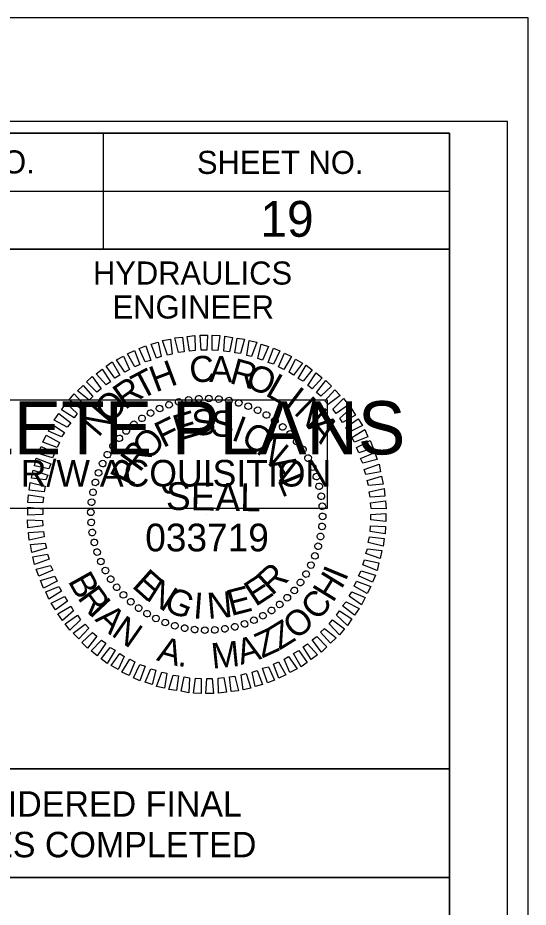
# Model space of a CAD drawing. Extents: x 1779926 to 1781610, y 602514 to 621564.
# Drawn here: x 1781499.5 to 1781610, y 603422 to 603614.5 of the extents above; entities that cross this region are included whole.
import ezdxf

# ---------------------------------------------------------------- set-up
doc = ezdxf.new("R2010")
doc.units = 0
for name, color, linetype in [('Old_Level_58', 7, 'Continuous'), ('Sheet Data Field CELL', 7, 'Continuous'), ('Sheet Plot Border Inside CELL', 7, 'Continuous'), ('Sheet Plot Border Outside CELL', 7, 'Continuous'), ('Sheet Professional Seal CELL', 7, 'Continuous'), ('Sheet Profile CELL', 7, 'Continuous'), ('Sheet Profile Grid Major CELL', 7, 'Continuous'), ('Sheet Profile Grid Minor CELL', 7, 'Continuous'), ('Sheet Sticker Exception Certification CELL', 7, 'Continuous'), ('Sheet Sticker Incomplete CELL', 7, 'Continuous')]:
    doc.layers.add(name, color=color, linetype=linetype)

msp = doc.modelspace()

# ---------------------------------------------------------------- linework, layer by layer
at = {"layer": 'Old_Level_58'}
msp.add_lwpolyline([(1781392.96, 603428.4), (1781592.95, 603428.4), (1781592.95, 603364.45), (1781392.96, 603364.45)], close=True, dxfattribs=at)
at = {"layer": 'Sheet Plot Border Inside CELL'}
msp.add_lwpolyline([(1779938.96, 602536.9), (1781605.46, 602536.9), (1781605.46, 603592), (1779938.96, 603592)], close=True, dxfattribs=at)
at = {"layer": 'Sheet Plot Border Outside CELL'}
msp.add_lwpolyline([(1779925.96, 602514.45), (1781609.96, 602514.45), (1781609.96, 603614.45), (1779925.96, 603614.45)], close=True, dxfattribs=at)
at = {"layer": 'Sheet Professional Seal CELL'}
for p, q in [((1781538.64, 603532.03), (1781538.64, 603532.03)), ((1781540.84, 603532.08), (1781540.84, 603532.08)), ((1781543.04, 603531.93), (1781543.04, 603531.93)), ((1781530.19, 603529.93), (1781530.19, 603529.93)), ((1781532.19, 603530.73), (1781532.19, 603530.73)), ((1781534.29, 603531.33), (1781534.29, 603531.33)), ((1781536.49, 603531.73), (1781536.49, 603531.73)), ((1781545.19, 603531.58), (1781545.19, 603531.58)), ((1781547.29, 603531.13), (1781547.29, 603531.13)), ((1781549.39, 603530.43), (1781549.39, 603530.43)), ((1781528.24, 603528.93), (1781528.24, 603528.93)), ((1781551.39, 603529.53), (1781551.39, 603529.53)), ((1781553.34, 603528.53), (1781553.34, 603528.53)), ((1781524.59, 603526.53), (1781524.59, 603526.53)), ((1781526.34, 603527.78), (1781526.34, 603527.78)), ((1781555.14, 603527.28), (1781555.14, 603527.28)), ((1781522.94, 603525.03), (1781522.94, 603525.03)), ((1781556.89, 603525.93), (1781556.89, 603525.93)), ((1781558.44, 603524.43), (1781558.44, 603524.43)), ((1781521.44, 603523.48), (1781521.44, 603523.48)), ((1781559.94, 603522.78), (1781559.94, 603522.78)), ((1781520.09, 603521.73), (1781520.09, 603521.73)), ((1781561.19, 603521.03), (1781561.19, 603521.03)), ((1781518.84, 603519.93), (1781518.84, 603519.93)), ((1781562.34, 603519.13), (1781562.34, 603519.13)), ((1781517.84, 603517.98), (1781517.84, 603517.98)), ((1781563.34, 603517.18), (1781563.34, 603517.18)), ((1781516.94, 603515.98), (1781516.94, 603515.98)), ((1781564.14, 603515.18), (1781564.14, 603515.18)), ((1781516.24, 603513.88), (1781516.24, 603513.88)), ((1781564.74, 603513.08), (1781564.74, 603513.08)), ((1781515.79, 603511.78), (1781515.79, 603511.78)), ((1781565.14, 603510.88), (1781565.14, 603510.88)), ((1781515.44, 603509.63), (1781515.44, 603509.63)), ((1781565.44, 603508.73), (1781565.44, 603508.73)), ((1781515.29, 603507.43), (1781515.29, 603507.43)), ((1781540.39, 603506.98), (1781540.39, 603506.98)), ((1781515.34, 603505.23), (1781515.34, 603505.23)), ((1781565.49, 603506.53), (1781565.49, 603506.53)), ((1781515.64, 603503.08), (1781515.64, 603503.08)), ((1781565.34, 603504.33), (1781565.34, 603504.33)), ((1781564.99, 603502.18), (1781564.99, 603502.18)), ((1781516.04, 603500.88), (1781516.04, 603500.88)), ((1781564.54, 603500.08), (1781564.54, 603500.08)), ((1781516.64, 603498.78), (1781516.64, 603498.78)), ((1781563.84, 603497.98), (1781563.84, 603497.98)), ((1781517.44, 603496.78), (1781517.44, 603496.78)), ((1781562.94, 603495.98), (1781562.94, 603495.98)), ((1781518.44, 603494.83), (1781518.44, 603494.83)), ((1781561.94, 603494.03), (1781561.94, 603494.03)), ((1781519.59, 603492.93), (1781519.59, 603492.93)), ((1781560.69, 603492.23), (1781560.69, 603492.23)), ((1781520.84, 603491.18), (1781520.84, 603491.18)), ((1781522.34, 603489.53), (1781522.34, 603489.53)), ((1781559.34, 603490.48), (1781559.34, 603490.48)), ((1781523.89, 603488.03), (1781523.89, 603488.03)), ((1781557.84, 603488.93), (1781557.84, 603488.93)), ((1781525.64, 603486.68), (1781525.64, 603486.68)), ((1781554.44, 603486.18), (1781554.44, 603486.18)), ((1781556.19, 603487.43), (1781556.19, 603487.43)), ((1781527.44, 603485.43), (1781527.44, 603485.43)), ((1781529.39, 603484.43), (1781529.39, 603484.43)), ((1781550.59, 603484.03), (1781550.59, 603484.03)), ((1781552.54, 603485.03), (1781552.54, 603485.03)), ((1781531.39, 603483.53), (1781531.39, 603483.53)), ((1781533.49, 603482.83), (1781533.49, 603482.83)), ((1781535.59, 603482.38), (1781535.59, 603482.38)), ((1781537.74, 603482.03), (1781537.74, 603482.03)), ((1781539.94, 603481.88), (1781539.94, 603481.88)), ((1781542.14, 603481.93), (1781542.14, 603481.93)), ((1781544.29, 603482.23), (1781544.29, 603482.23)), ((1781546.49, 603482.63), (1781546.49, 603482.63)), ((1781548.59, 603483.23), (1781548.59, 603483.23))]:
    msp.add_line(p, q, dxfattribs=at)
for points in [[(1781534.29, 603541.98), (1781533.49, 603545.18), (1781535.14, 603545.33), (1781535.49, 603542.13)], [(1781536.69, 603542.28), (1781536.14, 603545.48), (1781537.84, 603545.68), (1781537.89, 603542.43)], [(1781539.19, 603542.53), (1781538.94, 603545.78), (1781540.59, 603545.73), (1781540.39, 603542.48)], [(1781541.59, 603542.48), (1781541.59, 603545.73), (1781543.24, 603545.68), (1781542.79, 603542.43)], [(1781544.09, 603542.33), (1781544.29, 603545.58), (1781545.94, 603545.28), (1781545.29, 603542.13)], [(1781527.04, 603539.98), (1781525.74, 603542.88), (1781527.24, 603543.48), (1781528.29, 603540.28)], [(1781529.49, 603540.78), (1781528.34, 603543.78), (1781529.89, 603544.23), (1781530.54, 603541.13)], [(1781531.89, 603541.43), (1781530.84, 603544.58), (1781532.54, 603544.93), (1781532.94, 603541.68)], [(1781546.49, 603541.93), (1781546.94, 603545.13), (1781548.59, 603544.88), (1781547.69, 603541.78)], [(1781549.04, 603541.38), (1781549.54, 603544.63), (1781551.24, 603544.23), (1781550.09, 603541.13)], [(1781551.44, 603540.73), (1781552.19, 603543.83), (1781553.74, 603543.33), (1781552.49, 603540.38)], [(1781524.84, 603538.93), (1781523.24, 603541.73), (1781524.79, 603542.43), (1781525.94, 603539.38)], [(1781553.69, 603539.83), (1781554.84, 603542.98), (1781556.24, 603542.38), (1781554.84, 603539.48)], [(1781555.94, 603538.88), (1781557.19, 603541.83), (1781558.74, 603541.13), (1781557.04, 603538.33)], [(1781520.49, 603536.48), (1781518.64, 603539.03), (1781519.94, 603539.98), (1781521.59, 603537.08)], [(1781522.69, 603537.73), (1781520.84, 603540.43), (1781522.39, 603541.23), (1781523.64, 603538.33)], [(1781558.24, 603537.73), (1781559.59, 603540.58), (1781561.09, 603539.73), (1781559.19, 603537.13)], [(1781518.59, 603534.98), (1781516.44, 603537.38), (1781517.79, 603538.43), (1781519.54, 603535.63)], [(1781560.19, 603536.38), (1781561.94, 603539.28), (1781563.24, 603538.23), (1781561.29, 603535.78)], [(1781562.24, 603534.88), (1781564.09, 603537.63), (1781565.39, 603536.53), (1781563.19, 603534.18)], [(1781516.59, 603533.43), (1781514.39, 603535.63), (1781515.59, 603536.83), (1781517.54, 603534.13)], [(1781564.14, 603533.33), (1781566.19, 603535.93), (1781567.39, 603534.73), (1781565.09, 603532.58)], [(1781514.94, 603531.68), (1781512.39, 603533.73), (1781513.64, 603534.88), (1781515.74, 603532.48)], [(1781565.94, 603531.58), (1781568.09, 603533.93), (1781569.29, 603532.73), (1781566.69, 603530.78)], [(1781513.19, 603529.78), (1781510.59, 603531.73), (1781511.69, 603533.03), (1781513.89, 603530.68)], [(1781567.69, 603529.78), (1781569.99, 603532.03), (1781571.04, 603530.68), (1781568.39, 603528.78)], [(1781511.69, 603527.88), (1781508.99, 603529.58), (1781509.94, 603531.03), (1781512.34, 603528.83)], [(1781569.19, 603527.83), (1781571.64, 603529.93), (1781572.59, 603528.48), (1781569.79, 603526.88)], [(1781510.19, 603525.88), (1781507.39, 603527.38), (1781508.39, 603528.78), (1781510.99, 603526.78)], [(1781508.99, 603523.73), (1781506.14, 603524.98), (1781506.89, 603526.53), (1781509.59, 603524.68)], [(1781570.49, 603525.78), (1781573.14, 603527.68), (1781574.09, 603526.18), (1781571.19, 603524.78)], [(1781507.99, 603521.43), (1781504.89, 603522.58), (1781505.64, 603524.13), (1781508.49, 603522.53)], [(1781571.79, 603523.58), (1781574.59, 603525.33), (1781575.24, 603523.78), (1781572.39, 603522.63)], [(1781572.79, 603521.43), (1781575.74, 603522.93), (1781576.39, 603521.33), (1781573.29, 603520.33)], [(1781506.99, 603519.23), (1781503.89, 603520.13), (1781504.54, 603521.68), (1781507.54, 603520.28)], [(1781573.69, 603519.08), (1781576.74, 603520.38), (1781577.29, 603518.83), (1781574.19, 603518.03)], [(1781506.24, 603516.83), (1781503.14, 603517.48), (1781503.49, 603519.13), (1781506.64, 603517.88)], [(1781505.59, 603514.43), (1781502.49, 603514.83), (1781502.84, 603516.53), (1781505.99, 603515.48)], [(1781574.49, 603516.68), (1781577.69, 603517.83), (1781577.99, 603516.18), (1781574.84, 603515.63)], [(1781575.09, 603514.28), (1781578.24, 603515.23), (1781578.54, 603513.53), (1781575.39, 603513.23)], [(1781505.19, 603511.88), (1781501.99, 603512.18), (1781502.19, 603513.88), (1781505.44, 603513.08)], [(1781575.54, 603511.88), (1781578.79, 603512.58), (1781578.94, 603510.88), (1781575.74, 603510.68)], [(1781504.94, 603509.48), (1781501.69, 603509.58), (1781501.79, 603511.23), (1781505.04, 603510.68)], [(1781575.84, 603509.48), (1781579.09, 603509.88), (1781579.19, 603508.18), (1781575.94, 603508.28)], [(1781504.89, 603506.98), (1781501.64, 603506.83), (1781501.64, 603508.53), (1781504.89, 603508.18)], [(1781575.89, 603506.98), (1781579.14, 603507.13), (1781579.14, 603505.43), (1781575.89, 603505.78)], [(1781504.94, 603504.48), (1781501.69, 603504.08), (1781501.59, 603505.78), (1781504.84, 603505.68)], [(1781505.24, 603502.08), (1781501.99, 603501.38), (1781501.84, 603503.08), (1781505.04, 603503.28)], [(1781575.84, 603504.48), (1781579.09, 603504.38), (1781578.99, 603502.73), (1781575.74, 603503.28)], [(1781575.59, 603502.08), (1781578.79, 603501.78), (1781578.59, 603500.08), (1781575.34, 603500.88)], [(1781505.69, 603499.68), (1781502.54, 603498.73), (1781502.24, 603500.43), (1781505.39, 603500.73)], [(1781575.19, 603499.53), (1781578.29, 603499.13), (1781577.94, 603497.43), (1781574.79, 603498.48)], [(1781506.29, 603497.28), (1781503.09, 603496.13), (1781502.79, 603497.78), (1781505.94, 603498.33)], [(1781574.54, 603497.13), (1781577.64, 603496.48), (1781577.29, 603494.83), (1781574.14, 603496.08)], [(1781507.09, 603494.88), (1781504.04, 603493.58), (1781503.49, 603495.13), (1781506.59, 603495.93)], [(1781507.99, 603492.53), (1781505.04, 603491.03), (1781504.39, 603492.63), (1781507.49, 603493.63)], [(1781573.79, 603494.73), (1781576.89, 603493.83), (1781576.24, 603492.28), (1781573.24, 603493.68)], [(1781572.79, 603492.53), (1781575.89, 603491.38), (1781575.14, 603489.83), (1781572.29, 603491.43)], [(1781508.99, 603490.38), (1781506.19, 603488.63), (1781505.54, 603490.18), (1781508.39, 603491.33)], [(1781571.79, 603490.23), (1781574.64, 603488.98), (1781573.89, 603487.43), (1781571.19, 603489.28)], [(1781510.29, 603488.18), (1781507.64, 603486.28), (1781506.69, 603487.78), (1781509.59, 603489.18)], [(1781570.59, 603488.08), (1781573.39, 603486.58), (1781572.39, 603485.18), (1781569.79, 603487.18)], [(1781511.59, 603486.13), (1781509.14, 603484.03), (1781508.19, 603485.48), (1781510.99, 603487.08)], [(1781569.09, 603486.08), (1781571.79, 603484.38), (1781570.84, 603482.93), (1781568.44, 603485.13)], [(1781513.09, 603484.18), (1781510.79, 603481.93), (1781509.74, 603483.28), (1781512.39, 603485.18)], [(1781567.59, 603484.18), (1781570.19, 603482.23), (1781569.09, 603480.93), (1781566.89, 603483.28)], [(1781514.84, 603482.38), (1781512.69, 603480.03), (1781511.49, 603481.23), (1781514.09, 603483.18)], [(1781565.84, 603482.28), (1781568.39, 603480.23), (1781567.14, 603479.08), (1781565.04, 603481.48)], [(1781516.64, 603480.63), (1781514.59, 603478.03), (1781513.39, 603479.23), (1781515.69, 603481.38)], [(1781564.19, 603480.53), (1781566.39, 603478.33), (1781565.19, 603477.13), (1781563.24, 603479.83)], [(1781518.54, 603479.08), (1781516.69, 603476.33), (1781515.39, 603477.43), (1781517.59, 603479.78)], [(1781520.59, 603477.58), (1781518.84, 603474.68), (1781517.54, 603475.73), (1781519.49, 603478.18)], [(1781562.19, 603478.98), (1781564.34, 603476.58), (1781562.99, 603475.53), (1781561.24, 603478.33)], [(1781522.54, 603476.23), (1781521.19, 603473.38), (1781519.69, 603474.23), (1781521.59, 603476.83)], [(1781558.09, 603476.23), (1781559.94, 603473.53), (1781558.39, 603472.73), (1781557.14, 603475.63)], [(1781560.29, 603477.48), (1781562.14, 603474.93), (1781560.84, 603473.98), (1781559.19, 603476.88)], [(1781524.84, 603475.08), (1781523.59, 603472.13), (1781522.04, 603472.83), (1781523.74, 603475.63)], [(1781527.09, 603474.13), (1781525.94, 603470.98), (1781524.54, 603471.58), (1781525.94, 603474.48)], [(1781555.94, 603475.03), (1781557.54, 603472.23), (1781555.99, 603471.53), (1781554.84, 603474.58)], [(1781529.34, 603473.23), (1781528.59, 603470.13), (1781527.04, 603470.63), (1781528.29, 603473.58)], [(1781531.74, 603472.58), (1781531.24, 603469.33), (1781529.54, 603469.73), (1781530.69, 603472.83)], [(1781534.29, 603472.03), (1781533.84, 603468.83), (1781532.19, 603469.08), (1781533.09, 603472.18)], [(1781548.89, 603472.53), (1781549.94, 603469.38), (1781548.24, 603469.03), (1781547.84, 603472.28)], [(1781551.29, 603473.18), (1781552.44, 603470.18), (1781550.89, 603469.73), (1781550.24, 603472.83)], [(1781553.74, 603473.98), (1781555.04, 603471.08), (1781553.54, 603470.48), (1781552.49, 603473.68)], [(1781536.69, 603471.63), (1781536.49, 603468.38), (1781534.84, 603468.68), (1781535.49, 603471.83)], [(1781539.19, 603471.48), (1781539.19, 603468.23), (1781537.54, 603468.28), (1781537.99, 603471.53)], [(1781541.59, 603471.43), (1781541.84, 603468.18), (1781540.19, 603468.23), (1781540.39, 603471.48)], [(1781544.09, 603471.68), (1781544.64, 603468.48), (1781542.94, 603468.28), (1781542.89, 603471.53)], [(1781546.49, 603471.98), (1781547.29, 603468.78), (1781545.64, 603468.63), (1781545.29, 603471.83)]]:
    msp.add_lwpolyline(points, close=True, dxfattribs=at)
for centre, major_axis in [((1781534.33, 603531.31), (-0.174, 0.699)), ((1781536.47, 603531.75), (-0.113, 0.711)), ((1781538.65, 603532), (-0.05, 0.718)), ((1781540.83, 603532.05), (0.013, 0.72)), ((1781543.02, 603531.92), (0.075, 0.716)), ((1781545.18, 603531.6), (0.137, 0.707)), ((1781547.31, 603531.09), (0.198, 0.692)), ((1781530.19, 603529.89), (-0.293, 0.658)), ((1781532.23, 603530.69), (-0.234, 0.681)), ((1781549.38, 603530.39), (0.258, 0.672)), ((1781551.39, 603529.52), (0.316, 0.647)), ((1781526.37, 603527.77), (-0.403, 0.597)), ((1781528.24, 603528.91), (-0.349, 0.63)), ((1781553.31, 603528.48), (0.371, 0.617)), ((1781555.14, 603527.27), (0.423, 0.582)), ((1781524.61, 603526.47), (-0.453, 0.56)), ((1781556.85, 603525.91), (0.472, 0.543)), ((1781521.47, 603523.43), (-0.543, 0.472)), ((1781522.97, 603525.02), (-0.5, 0.518)), ((1781558.44, 603524.4), (0.518, 0.5)), ((1781520.1, 603521.72), (-0.582, 0.423)), ((1781559.89, 603522.76), (0.56, 0.453)), ((1781518.9, 603519.9), (-0.617, 0.371)), ((1781561.19, 603521), (0.597, 0.403)), ((1781517.85, 603517.97), (-0.647, 0.316)), ((1781562.33, 603519.14), (0.63, 0.349)), ((1781516.98, 603515.97), (-0.672, 0.258)), ((1781563.31, 603517.18), (0.658, 0.293)), ((1781516.29, 603513.89), (-0.692, 0.198)), ((1781564.11, 603515.14), (0.681, 0.234)), ((1781515.78, 603511.76), (-0.707, 0.137)), ((1781564.73, 603513.05), (0.699, 0.174)), ((1781565.17, 603510.9), (0.711, 0.113)), ((1781515.45, 603509.6), (-0.716, 0.075)), ((1781565.41, 603508.73), (0.718, 0.05)), ((1781515.32, 603507.42), (-0.72, 0.013)), ((1781565.47, 603506.54), (0.72, -0.013)), ((1781515.38, 603505.23), (-0.718, -0.05)), ((1781565.34, 603504.36), (0.716, -0.075)), ((1781515.62, 603503.06), (-0.711, -0.113)), ((1781565.01, 603502.19), (0.707, -0.137)), ((1781516.06, 603500.91), (-0.699, -0.174)), ((1781516.68, 603498.81), (-0.681, -0.234)), ((1781564.5, 603500.07), (0.692, -0.198)), ((1781517.48, 603496.78), (-0.658, -0.293)), ((1781563.81, 603497.99), (0.672, -0.258)), ((1781518.46, 603494.82), (-0.63, -0.349)), ((1781562.94, 603495.98), (0.647, -0.316)), ((1781519.6, 603492.95), (-0.597, -0.403)), ((1781561.89, 603494.06), (0.617, -0.371)), ((1781520.9, 603491.2), (-0.56, -0.453)), ((1781560.68, 603492.24), (0.582, -0.423)), ((1781522.35, 603489.56), (-0.518, -0.5)), ((1781557.82, 603488.94), (0.5, -0.518)), ((1781559.32, 603490.52), (0.543, -0.472)), ((1781523.94, 603488.05), (-0.472, -0.543)), ((1781525.65, 603486.69), (-0.423, -0.582)), ((1781556.18, 603487.49), (0.453, -0.56)), ((1781527.48, 603485.48), (-0.371, -0.617)), ((1781552.55, 603485.04), (0.349, -0.63)), ((1781554.42, 603486.19), (0.403, -0.597)), ((1781529.4, 603484.44), (-0.316, -0.647)), ((1781531.41, 603483.56), (-0.258, -0.672)), ((1781533.48, 603482.87), (-0.198, -0.692)), ((1781548.56, 603483.27), (0.234, -0.681)), ((1781550.6, 603484.07), (0.293, -0.658)), ((1781535.61, 603482.36), (-0.137, -0.707)), ((1781537.77, 603482.04), (-0.075, -0.716)), ((1781539.96, 603481.9), (-0.013, -0.72)), ((1781542.14, 603481.96), (0.05, -0.718)), ((1781544.32, 603482.21), (0.113, -0.711)), ((1781546.46, 603482.64), (0.174, -0.699))]:
    msp.add_ellipse(centre, major_axis=major_axis, ratio=0.999708, dxfattribs=at)
at = {"layer": 'Sheet Profile CELL'}
for p, q in [((1781517.96, 603589.4), (1781517.96, 603564.4)), ((1781392.91, 603576.9), (1781592.96, 603576.9))]:
    msp.add_line(p, q, dxfattribs=at)
for points in [[(1781592.96, 603589.45), (1780092.96, 603589.45), (1780092.96, 602539.45), (1781592.96, 602539.45)], [(1781392.91, 603589.45), (1781592.96, 603589.45), (1781592.96, 603564.4), (1781392.91, 603564.4)], [(1781492.96, 603564.4), (1781592.96, 603564.4), (1781592.96, 603451.9), (1781492.96, 603451.9)]]:
    msp.add_lwpolyline(points, close=True, dxfattribs=at)
at = {"layer": 'Sheet Profile Grid Major CELL'}
msp.add_lwpolyline([(1781542.96, 603364.45), (1781542.96, 603089.45), (1781592.96, 603089.45), (1781592.96, 603439.45)], dxfattribs=at)
at = {"layer": 'Sheet Sticker Exception Certification CELL'}
for p, q in [((1781392.91, 603451.9), (1781592.95, 603451.9)), ((1781392.91, 603451.9), (1781592.95, 603451.9)), ((1781592.95, 603451.89), (1781592.95, 603428.39)), ((1781592.95, 603451.89), (1781592.95, 603428.39)), ((1781592.95, 603428.4), (1781392.91, 603428.4)), ((1781592.95, 603428.4), (1781392.91, 603428.4))]:
    msp.add_line(p, q, dxfattribs=at)
at = {"layer": 'Sheet Sticker Incomplete CELL'}
msp.add_lwpolyline([(1781419.48, 603508.25), (1781419.48, 603531.75), (1781566.48, 603531.75), (1781566.48, 603508.25)], close=True, dxfattribs=at)

# ---------------------------------------------------------------- texts
at = {"layer": 'Sheet Data Field CELL'}
msp.add_text('19', height=7.75, dxfattribs=at).set_placement((1781552, 603567.06))
at = {"layer": 'Sheet Professional Seal CELL'}
for s, height, rotation, p in [('C', 5.64, 6.2199, (1781536.94, 603535.33)), ('H', 5.64, 20.6195, (1781529.34, 603533.33)), ('A', 5.64, 359.0203, (1781540.89, 603535.63)), ('R', 5.64, 344.6211, (1781545.09, 603535.43)), ('T', 5.64, 27.8198, (1781526.09, 603531.68)), ('O', 5.64, 337.4212, (1781548.44, 603534.68)), ('R', 5.64, 35.0205, (1781522.69, 603529.48)), ('L', 5.64, 330.2209, (1781552.84, 603532.83)), ('I', 5.64, 323.0201, (1781556.89, 603530.43)), ('O', 5.64, 42.2217, (1781519.24, 603526.38)), ('N', 5.64, 315.8189, (1781559.04, 603528.88)), ('N', 5.64, 49.4235, (1781516.94, 603523.48)), ('S', 5.64, 7.2556, (1781537.59, 603523.83)), ('F', 5.64, 25.967, (1781530.94, 603521.28)), ('E', 5.64, 16.6111, (1781534.14, 603522.78)), ('S', 5.64, 357.9004, (1781541.19, 603523.88)), ('I', 5.64, 339.1896, (1781545.49, 603523.18)), ('O', 5.64, 329.8335, (1781547.49, 603522.48)), ('A', 5.64, 308.6172, (1781561.99, 603525.93)), ('O', 5.64, 44.6812, (1781527.64, 603518.33)), ('N', 5.64, 320.4766, (1781550.84, 603520.48)), ('R', 5.64, 54.0397, (1781525.89, 603515.88)), ('P', 5.64, 63.3989, (1781524.29, 603512.68)), ('A', 5.64, 301.7603, (1781553.69, 603517.88)), ('L', 5.64, 292.4008, (1781555.64, 603514.43)), ('SEAL', 5.998, 359, (1781531.54, 603507.98)), ('R', 5.64, 42.4814, (1781554.49, 603489.23)), ('E', 5.64, 318.2769, (1781523.99, 603491.33)), ('E', 5.64, 33.1241, (1781550.94, 603486.88)), ('N', 5.64, 327.634, (1781526.99, 603488.63)), ('E', 5.64, 14.4118, (1781545.64, 603484.93)), ('G', 5.64, 336.9902, (1781530.79, 603486.38)), ('I', 5.64, 355.7012, (1781537.34, 603484.48)), ('N', 5.64, 5.0564, (1781540.69, 603484.33))]:
    msp.add_text(s, height=height, rotation=rotation, dxfattribs=at).set_placement(p)
at = {"layer": 'Sheet Profile CELL'}
for s, height, p in [('PROJECT REFERENCE NO.', 5.0001, (1781415.12, 603580.76)), ('SHEET NO.', 5, (1781538.27, 603580.66)), ('HYDRAULICS', 5, (1781515.77, 603556.71)), ('ENGINEER', 5, (1781520.02, 603549.36))]:
    msp.add_text(s, height=height, dxfattribs=at).set_placement(p)
at = {"layer": 'Sheet Profile Grid Minor CELL'}
msp.add_text('033719', height=5.998, dxfattribs=at).set_placement((1781527.08, 603498.97))
for s, rotation, p in [('I', 67.5926, (1781570.45, 603492.34)), ('B', 299.1529, (1781510.25, 603492.54)), ('H', 58.3478, (1781567.71, 603487.7)), ('R', 306.2797, (1781512.27, 603488.91)), ('C', 49.4751, (1781564.41, 603483.72)), ('I', 313.2061, (1781514.66, 603485.65)), ('A', 316.7266, (1781516.01, 603484.11)), ('O', 38.7706, (1781559.67, 603479.67)), ('N', 324.9124, (1781519.52, 603480.87)), ('Z', 31.6438, (1781556.13, 603477.49)), ('Z', 24.517, (1781552.35, 603475.76)), ('A', 344.2893, (1781529.36, 603475.42)), ('A', 16.3312, (1781547.78, 603474.38)), ('M', 5.6554, (1781541.62, 603473.57)), ('.', 352.4751, (1781533.97, 603474.17))]:
    msp.add_text(s, height=5.5, rotation=rotation, dxfattribs=at).set_placement(p)
at = {"layer": 'Sheet Sticker Exception Certification CELL'}
for s, p in [('DOCUMENT NOT CONSIDERED FINAL', (1781413.98, 603441.56)), ('DOCUMENT NOT CONSIDERED FINAL', (1781413.98, 603441.56)), ('UNLESS ALL SIGNATURES COMPLETED', (1781408.91, 603432.76)), ('UNLESS ALL SIGNATURES COMPLETED', (1781408.91, 603432.76))]:
    msp.add_text(s, height=5.5, dxfattribs=at).set_placement(p)
at = {"layer": 'Sheet Sticker Incomplete CELL'}
for s, height, p in [('INCOMPLETE PLANS', 11.52, (1781428.43, 603519.95)), ('DO NOT USE FOR R/W ACQUISITION', 5.76, (1781431.68, 603513))]:
    msp.add_text(s, height=height, dxfattribs=at).set_placement(p)

doc.saveas('drawing.dxf')
